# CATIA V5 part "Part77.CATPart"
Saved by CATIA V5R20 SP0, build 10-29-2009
Part number: FA 053000-3
Revision: ANY
Definition: UNKNOWN
Nomenclature: FA 053000-3
Source: Unknown
Bounding box of the stored display mesh (mm): x 0 to 2, y -1.45 to 1.45, z -1.45 to 1.45
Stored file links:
  C:\Users\Utente\Desktop\IO LAVORO\3D X SITO CF\CUMSA\3D files FA\FA 053004-21\Part77.CATPart

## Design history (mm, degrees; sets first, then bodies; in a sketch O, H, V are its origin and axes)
Body1 "Revolución1" (main body)
  Solid1: solid without history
